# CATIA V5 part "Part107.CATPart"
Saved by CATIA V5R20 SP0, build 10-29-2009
Part number: FA 063200-2 - comprimido
Revision: ANY
Definition: UNKNOWN
Nomenclature: FA 063200-2 - comprimido
Source: Unknown
Bounding box of the stored display mesh (mm): x -1.95 to 1.95, y 0 to 5.85, z -1.95 to 1.95
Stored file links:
  C:\Users\Utente\Desktop\IO LAVORO\3D X SITO CF\CUMSA\3D files FA\FA 063212-20\Part107.CATPart

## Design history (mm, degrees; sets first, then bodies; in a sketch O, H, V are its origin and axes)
Body1 "Cortar-Extruir1" (main body)
  Solid1: solid without history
